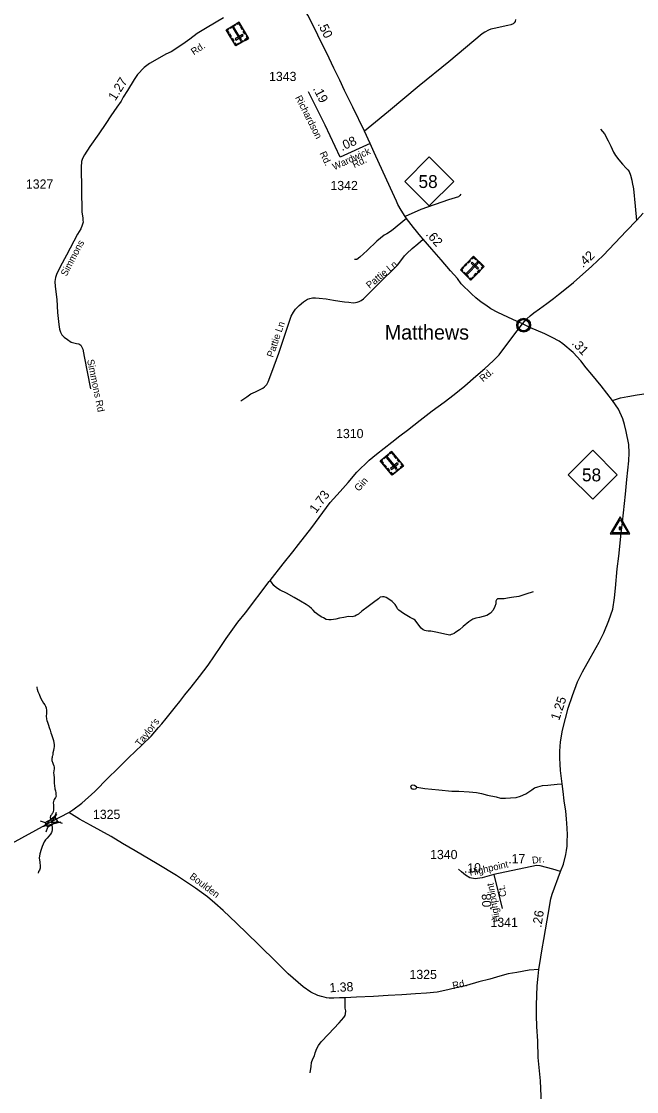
# Model space of a CAD drawing. Extents: x 2220236 to 2384410, y 720751 to 894131.
# Drawn here: x 2277880 to 2286237, y 831981 to 846519 of the extents above; entities that cross this region are included whole.
import ezdxf

# ---------------------------------------------------------------- set-up
doc = ezdxf.new("R2010")
doc.units = 0
doc.layers.add('Default', color=7, linetype='Continuous')

msp = doc.modelspace()

# ---------------------------------------------------------------- linework, layer by layer
at = {"layer": 'Default'}
for p, q in [((2278732, 841968), (2278817, 841529)), ((2278336, 835709), (2278356, 835775)), ((2278137, 835657), (2278203, 835637)), ((2278217, 835509), (2278237, 835575)), ((2278369, 835649), (2278435, 835629)), ((2284297, 834930), (2284410, 834469))]:
    msp.add_line(p, q, dxfattribs=at)
for points in [[(2282616, 844862), (2282542, 845029), (2282382, 845354), (2282268, 845580), (2282204, 845722), (2282126, 845883), (2282027, 846086), (2281958, 846230), (2281855, 846435), (2281769, 846605), (2281665, 846777), (2281569, 846930), (2281452, 847109), (2281389, 847193)], [(2280626, 846570), (2280403, 846438), (2280268, 846354), (2280169, 846280), (2280071, 846211), (2279914, 846107), (2279843, 846075), (2279692, 845990), (2279619, 845949), (2279548, 845895), (2279456, 845798), (2279412, 845731), (2279322, 845582), (2279264, 845489), (2279235, 845437), (2279174, 845353), (2279093, 845236), (2279028, 845131), (2278933, 844991), (2278811, 844820), (2278736, 844705), (2278711, 844659), (2278697, 844617), (2278691, 844540), (2278703, 843931), (2278714, 843847), (2278716, 843821), (2278717, 843791), (2278707, 843749), (2278685, 843703), (2278642, 843630), (2278493, 843345), (2278406, 843184), (2278355, 843080), (2278342, 843040), (2278336, 842984), (2278339, 842916), (2278359, 842740), (2278372, 842564), (2278388, 842400), (2278398, 842337), (2278411, 842297), (2278429, 842261), (2278463, 842229), (2278504, 842200), (2278558, 842164), (2278628, 842145), (2278658, 842139), (2278674, 842131), (2278688, 842119), (2278698, 842103), (2278715, 842066), (2278732, 841968)], [(2284591, 846544), (2284587, 846516), (2284574, 846499), (2284559, 846484), (2284527, 846473), (2284487, 846462), (2284304, 846422), (2284258, 846413), (2284227, 846402), (2284177, 846374), (2284141, 846351), (2283688, 845972), (2283283, 845645), (2282868, 845296), (2282639, 845111), (2282542, 845029)], [(2282211, 844677), (2282007, 845111), (2281778, 845562)], [(2285747, 845054), (2285800, 844991), (2285851, 844895), (2285886, 844824), (2285921, 844745), (2285951, 844696), (2285994, 844641), (2286047, 844578), (2286097, 844526), (2286117, 844505), (2286135, 844478), (2286155, 844431), (2286172, 844363), (2286178, 844329), (2286193, 844247), (2286218, 844011), (2286235, 843814)], [(2282616, 844862), (2282211, 844677)], [(2284687, 842410), (2284554, 842468), (2284350, 842566), (2284259, 842615), (2284187, 842663), (2284126, 842706), (2284054, 842766), (2283992, 842819), (2283856, 842952), (2283805, 843025), (2283708, 843133), (2283581, 843281), (2283456, 843427), (2283337, 843562), (2283307, 843595), (2283204, 843720), (2283109, 843843), (2283092, 843867), (2283038, 843957), (2282995, 844034), (2282974, 844078), (2282892, 844252), (2282671, 844740), (2282616, 844862)], [(2283851, 844173), (2283835, 844153), (2283819, 844137), (2283681, 844095), (2283305, 843963), (2283092, 843867)], [(2283109, 843843), (2282909, 843675), (2282842, 843634), (2282810, 843615), (2282709, 843535), (2282579, 843409), (2282477, 843318), (2282438, 843285), (2282404, 843283)], [(2284687, 842410), (2284748, 842478), (2284790, 842518), (2284839, 842559), (2284919, 842614), (2285016, 842689), (2285106, 842753), (2285175, 842808), (2285260, 842879), (2285379, 842974), (2285629, 843194), (2285784, 843339), (2286102, 843672), (2286235, 843814), (2286325, 843913)], [(2280860, 841363), (2280940, 841419), (2280998, 841460), (2281060, 841488), (2281097, 841507), (2281131, 841523), (2281159, 841538), (2281183, 841557), (2281213, 841585), (2281232, 841622), (2281284, 841755), (2281376, 842011), (2281482, 842325), (2281546, 842517), (2281574, 842571), (2281604, 842612), (2281654, 842659), (2281714, 842711), (2281766, 842745), (2281796, 842756), (2281833, 842762), (2281876, 842765), (2281923, 842758), (2282018, 842749), (2282119, 842732), (2282207, 842717), (2282269, 842709), (2282327, 842704), (2282385, 842698), (2282418, 842702), (2282441, 842706), (2282469, 842715), (2282497, 842728), (2282529, 842749), (2282583, 842805), (2282699, 842922), (2282809, 843029), (2282906, 843126), (2282988, 843210), (2283033, 843266), (2283084, 843335), (2283117, 843367), (2283190, 843432), (2283263, 843499), (2283337, 843562)], [(2278523, 835771), (2278579, 835808), (2278700, 835897), (2278879, 836056), (2279058, 836244), (2279179, 836360), (2279278, 836458), (2279340, 836521), (2279424, 836599), (2279519, 836690), (2279643, 836809), (2279741, 836927), (2279788, 836978), (2279847, 837050), (2279919, 837139), (2279972, 837209), (2280031, 837280), (2280098, 837370), (2280186, 837477), (2280300, 837619), (2280418, 837775), (2280588, 838027), (2280663, 838136), (2280819, 838357), (2280923, 838484), (2281246, 838909), (2281257, 838922), (2281437, 839152), (2281565, 839315), (2281644, 839413), (2281824, 839644), (2282073, 839982), (2282208, 840135), (2282319, 840257), (2282438, 840394), (2282603, 840557), (2282702, 840640), (2282913, 840804), (2283020, 840891), (2283123, 840967), (2283298, 841101), (2283460, 841228), (2283623, 841348), (2283758, 841449), (2283903, 841567), (2284053, 841699), (2284176, 841805), (2284287, 841910), (2284371, 841991), (2284556, 842240), (2284687, 842410)], [(2285909, 841371), (2285756, 841567), (2285630, 841722), (2285554, 841815), (2285481, 841909), (2285374, 842022), (2285233, 842137), (2285183, 842174), (2285092, 842223), (2284990, 842273), (2284787, 842363), (2284687, 842410)], [(2285909, 841371), (2286020, 841404), (2286116, 841423), (2286243, 841445), (2286397, 841468), (2286647, 841490), (2286751, 841493), (2286875, 841489), (2287245, 841450), (2287519, 841429), (2287775, 841405), (2287835, 841400), (2288251, 841367), (2289207, 841269), (2289372, 841253), (2289755, 841209), (2290008, 841158), (2290508, 841026)], [(2285201, 834972), (2285242, 835070), (2285274, 835202), (2285284, 835258), (2285294, 835313), (2285296, 835379), (2285298, 835471), (2285294, 835559), (2285283, 835687), (2285275, 835791), (2285251, 835933), (2285239, 836058), (2285226, 836160), (2285205, 836342), (2285197, 836428), (2285193, 836512), (2285195, 836604), (2285203, 836733), (2285231, 836891), (2285273, 837049), (2285307, 837189), (2285365, 837363), (2285434, 837548), (2285500, 837682), (2285604, 837868), (2285727, 838086), (2285792, 838211), (2285860, 838381), (2285916, 838533), (2285935, 838687), (2285952, 838819), (2285974, 839084), (2285994, 839254), (2286027, 839567), (2286044, 839716), (2286086, 840099), (2286104, 840295), (2286131, 840548), (2286135, 840658), (2286131, 840770), (2286094, 840949), (2286074, 841044), (2286048, 841121), (2285990, 841251), (2285909, 841371)], [(2284833, 838772), (2284731, 838739), (2284638, 838709), (2284536, 838691), (2284483, 838682), (2284438, 838674), (2284397, 838674), (2284374, 838675), (2284362, 838675), (2284348, 838674), (2284337, 838668), (2284332, 838663), (2284327, 838653), (2284325, 838644), (2284325, 838607), (2284309, 838572), (2284287, 838519), (2284253, 838480), (2284201, 838450), (2284104, 838422), (2284055, 838412), (2284014, 838400), (2283958, 838364), (2283881, 838298), (2283832, 838252), (2283783, 838222), (2283760, 838205), (2283737, 838194), (2283718, 838189), (2283698, 838183), (2283656, 838190), (2283510, 838222), (2283440, 838234), (2283405, 838238), (2283377, 838241), (2283361, 838245), (2283338, 838252), (2283310, 838278), (2283265, 838335), (2283231, 838385), (2283208, 838401), (2283163, 838422), (2283070, 838475), (2283008, 838519), (2282991, 838537), (2282978, 838561), (2282956, 838598), (2282915, 838637), (2282859, 838679), (2282834, 838691), (2282806, 838700), (2282783, 838702), (2282755, 838696), (2282733, 838675), (2282661, 838626), (2282592, 838573), (2282504, 838507), (2282457, 838466), (2282432, 838452), (2282408, 838440), (2282373, 838431), (2282325, 838433), (2282260, 838421), (2282199, 838414), (2282153, 838401), (2282118, 838396), (2282086, 838389), (2282058, 838391), (2282020, 838396), (2281983, 838415), (2281951, 838431), (2281905, 838463), (2281871, 838489), (2281843, 838521), (2281819, 838545), (2281791, 838572), (2281748, 838596), (2281669, 838644), (2281585, 838691), (2281480, 838751), (2281395, 838795), (2281345, 838826), (2281311, 838858), (2281276, 838900), (2281257, 838922)], [(2278089, 837481), (2278089, 837468), (2278093, 837446), (2278102, 837416), (2278120, 837378), (2278141, 837330), (2278161, 837291), (2278181, 837258), (2278198, 837235), (2278206, 837215), (2278214, 837193), (2278220, 837156), (2278220, 837133), (2278219, 837109), (2278217, 837091), (2278217, 837073), (2278219, 837053), (2278221, 837039), (2278227, 837021), (2278233, 836999), (2278248, 836957), (2278256, 836925), (2278270, 836889), (2278281, 836855), (2278289, 836830), (2278304, 836792), (2278314, 836752), (2278320, 836721), (2278325, 836696), (2278324, 836674), (2278324, 836664), (2278322, 836645), (2278317, 836616), (2278309, 836582), (2278305, 836559), (2278302, 836541), (2278298, 836531), (2278296, 836518), (2278294, 836506), (2278293, 836494), (2278295, 836479), (2278307, 836444), (2278313, 836427), (2278319, 836408), (2278323, 836388), (2278325, 836370), (2278320, 836335), (2278318, 836316), (2278320, 836280), (2278324, 836250), (2278324, 836220), (2278325, 836198), (2278327, 836168), (2278329, 836137), (2278336, 836094), (2278342, 836068), (2278346, 836038), (2278348, 836014), (2278351, 835994), (2278349, 835984), (2278343, 835974), (2278335, 835963), (2278327, 835951), (2278321, 835938), (2278315, 835921), (2278313, 835903), (2278314, 835877), (2278318, 835839), (2278318, 835828), (2278318, 835814), (2278316, 835802), (2278311, 835784), (2278305, 835769), (2278299, 835759), (2278287, 835741), (2278275, 835727), (2278272, 835703), (2278287, 835642), (2278292, 835616), (2278299, 835554), (2278299, 835536), (2278295, 835514), (2278289, 835503), (2278275, 835479), (2278254, 835451), (2278230, 835424), (2278208, 835399)], [(2283253, 836116), (2283219, 836138), (2283197, 836144), (2283179, 836140), (2283169, 836128), (2283167, 836116), (2283175, 836102), (2283183, 836094), (2283199, 836092), (2283213, 836090), (2283233, 836096), (2283241, 836100), (2283253, 836116)], [(2283253, 836116), (2283360, 836100), (2283552, 836080), (2283726, 836062), (2283821, 836060), (2283961, 836052), (2284061, 836044), (2284131, 836032), (2284213, 836010), (2284328, 835986), (2284390, 835968), (2284426, 835966), (2284454, 835966), (2284522, 835970), (2284600, 835978), (2284660, 835996), (2284730, 836028), (2284815, 836080), (2284848, 836106), (2284894, 836122), (2284960, 836140), (2285032, 836144), (2285160, 836158), (2285226, 836160)], [(2278265, 835637), (2278299, 835656), (2278523, 835771)], [(2284910, 833639), (2284778, 833630), (2284609, 833600), (2284491, 833579), (2284380, 833549), (2284241, 833509), (2284095, 833470), (2283926, 833421), (2283766, 833384), (2283634, 833354), (2283528, 833333), (2283382, 833317), (2283234, 833308), (2283049, 833296), (2282862, 833285), (2282662, 833275), (2282430, 833264), (2282278, 833257), (2282203, 833253), (2282122, 833252), (2282061, 833252), (2282023, 833257), (2281992, 833263), (2281956, 833273), (2281907, 833287), (2281812, 833333), (2281708, 833405), (2281505, 833583), (2281360, 833724), (2281095, 833984), (2280800, 834270), (2280621, 834439), (2280509, 834543), (2280410, 834627), (2280246, 834744), (2279987, 834915), (2279722, 835073), (2279424, 835251), (2279255, 835353), (2279098, 835446), (2278818, 835599), (2278670, 835681), (2278523, 835771)], [(2276045, 834343), (2276146, 834426), (2276264, 834519), (2276369, 834605), (2276521, 834700), (2276882, 834881), (2278077, 835532), (2278265, 835637)], [(2278208, 835399), (2278191, 835374), (2278163, 835310), (2278149, 835268), (2278130, 835213), (2278130, 835208), (2278122, 835158), (2278127, 835127), (2278129, 835102), (2278131, 835081), (2278133, 835062), (2278135, 835044), (2278134, 835016), (2278124, 834991), (2278114, 834969), (2278106, 834948)], [(2284297, 834930), (2284137, 834886), (2284046, 834872), (2283971, 834884), (2283913, 834922), (2283859, 834966), (2283817, 835002)], [(2285201, 834972), (2285101, 835002), (2284929, 835050), (2284875, 835052), (2284297, 834930)], [(2284910, 833639), (2284938, 833809), (2284956, 833919), (2284976, 834045), (2285000, 834177), (2285022, 834311), (2285034, 834387), (2285074, 834598), (2285092, 834661), (2285201, 834972)], [(2285901, 829402), (2285785, 829557), (2285463, 830016), (2285317, 830226), (2285249, 830348), (2285174, 830485), (2285140, 830570), (2285088, 830714), (2285049, 830881), (2285033, 830958), (2285006, 831122), (2284979, 831400), (2284951, 831706), (2284930, 832126), (2284902, 832446), (2284894, 832666), (2284883, 832867), (2284876, 833013), (2284876, 833155), (2284886, 833417), (2284899, 833551), (2284910, 833639)], [(2281803, 832235), (2281815, 832323), (2281819, 832378), (2281840, 832425), (2281861, 832469), (2281872, 832506), (2281891, 832566), (2281914, 832608), (2281951, 832656), (2282053, 832761), (2282197, 832914), (2282262, 832988), (2282276, 833013), (2282282, 833039), (2282285, 833076), (2282278, 833113), (2282280, 833171), (2282278, 833257)]]:
    msp.add_lwpolyline(points, dxfattribs=at)
for points in [[(2280963, 846288), (2280792, 846187), (2280662, 846405), (2280833, 846507)], [(2280690, 846422), (2280696, 846412), (2280677, 846401), (2280698, 846366), (2280688, 846361), (2280662, 846405)], [(2280789, 846468), (2280716, 846425), (2280710, 846434), (2280783, 846478)], [(2280854, 846258), (2280870, 846267), (2280767, 846442), (2280750, 846432)], [(2280804, 846490), (2280810, 846480), (2280829, 846492), (2280850, 846457), (2280859, 846462), (2280833, 846507)], [(2280868, 846447), (2280891, 846410), (2280881, 846404), (2280859, 846441)], [(2280708, 846349), (2280730, 846312), (2280721, 846306), (2280698, 846343)], [(2280742, 846292), (2280764, 846255), (2280754, 846249), (2280732, 846287)], [(2280893, 846326), (2280883, 846342), (2280782, 846282), (2280792, 846266)], [(2280903, 846389), (2280925, 846352), (2280915, 846346), (2280893, 846383)], [(2280941, 846325), (2280931, 846320), (2280947, 846292), (2280912, 846271), (2280918, 846262), (2280963, 846288)], [(2280769, 846224), (2280779, 846230), (2280796, 846202), (2280830, 846223), (2280836, 846213), (2280792, 846187)], [(2280899, 846250), (2280855, 846224), (2280849, 846234), (2280893, 846260)], [(2283087, 844345), (2283420, 844678), (2283753, 844345), (2283420, 844012)], [(2284022, 843328), (2284164, 843188), (2283986, 843006), (2283844, 843146)], [(2283893, 843196), (2283923, 843227), (2283931, 843219), (2283901, 843188)], [(2284080, 843230), (2284066, 843243), (2283924, 843099), (2283938, 843086)], [(2283940, 843244), (2283970, 843275), (2283979, 843267), (2283948, 843236)], [(2284004, 843250), (2283991, 843237), (2284075, 843155), (2284088, 843168)], [(2283992, 843297), (2284000, 843289), (2284023, 843312), (2284052, 843283), (2284059, 843291), (2284022, 843328)], [(2284075, 843276), (2284112, 843239), (2284104, 843231), (2284067, 843268)], [(2284134, 843157), (2284126, 843165), (2284149, 843188), (2284120, 843217), (2284127, 843225), (2284164, 843188)], [(2283868, 843123), (2283876, 843131), (2283860, 843146), (2283888, 843175), (2283880, 843183), (2283844, 843146)], [(2283893, 843114), (2283954, 843054), (2283946, 843046), (2283885, 843106)], [(2284029, 843066), (2284059, 843097), (2284067, 843089), (2284037, 843058)], [(2284075, 843113), (2284105, 843144), (2284113, 843136), (2284083, 843105)], [(2283963, 843030), (2283971, 843038), (2283986, 843022), (2284015, 843051), (2284023, 843044), (2283986, 843006)], [(2284625, 842406), (2284626, 842411), (2284628, 842418), (2284631, 842425), (2284634, 842431), (2284637, 842436), (2284641, 842442), (2284645, 842446), (2284649, 842451), (2284655, 842455), (2284660, 842459), (2284665, 842462), (2284670, 842464), (2284676, 842466), (2284681, 842468), (2284686, 842469), (2284690, 842470), (2284695, 842471), (2284701, 842471), (2284705, 842471), (2284711, 842471), (2284716, 842470), (2284721, 842469), (2284726, 842468), (2284731, 842466), (2284738, 842463), (2284744, 842459), (2284749, 842456), (2284754, 842452), (2284757, 842449), (2284762, 842444), (2284765, 842439), (2284769, 842435), (2284772, 842430), (2284774, 842425), (2284776, 842420), (2284778, 842415), (2284779, 842410), (2284780, 842404), (2284781, 842399), (2284781, 842393), (2284781, 842388), (2284780, 842382), (2284779, 842376), (2284778, 842370), (2284776, 842364), (2284773, 842359), (2284770, 842353), (2284767, 842348), (2284764, 842343), (2284759, 842339), (2284754, 842334), (2284749, 842329), (2284744, 842326), (2284740, 842324), (2284733, 842320), (2284726, 842318), (2284720, 842316), (2284713, 842315), (2284709, 842314), (2284704, 842314), (2284699, 842314), (2284694, 842314), (2284689, 842315), (2284683, 842317), (2284678, 842318), (2284673, 842320), (2284669, 842322), (2284665, 842324), (2284658, 842328), (2284652, 842332), (2284647, 842337), (2284643, 842342), (2284640, 842346), (2284637, 842350), (2284633, 842357), (2284631, 842360), (2284629, 842364), (2284627, 842373), (2284625, 842380), (2284624, 842385), (2284624, 842391), (2284624, 842396), (2284624, 842402)], [(2283071, 840482), (2282918, 840354), (2282755, 840549), (2282907, 840677)], [(2282870, 840632), (2282805, 840577), (2282798, 840586), (2282863, 840640)], [(2282882, 840656), (2282889, 840647), (2282906, 840661), (2282932, 840630), (2282940, 840638), (2282907, 840677)], [(2282952, 840624), (2282980, 840591), (2282971, 840583), (2282943, 840616)], [(2285308, 840361), (2285641, 840694), (2285974, 840361), (2285641, 840028)], [(2282780, 840571), (2282787, 840562), (2282770, 840548), (2282796, 840517), (2282788, 840509), (2282755, 840549)], [(2282810, 840501), (2282838, 840468), (2282829, 840461), (2282801, 840494)], [(2282968, 840435), (2282983, 840447), (2282852, 840602), (2282838, 840590)], [(2282996, 840508), (2282984, 840522), (2282894, 840447), (2282906, 840432)], [(2282995, 840572), (2283023, 840539), (2283014, 840532), (2282987, 840565)], [(2283043, 840515), (2283034, 840508), (2283055, 840483), (2283024, 840457), (2283031, 840449), (2283071, 840482)], [(2282852, 840451), (2282880, 840418), (2282871, 840410), (2282843, 840443)], [(2282890, 840387), (2282899, 840395), (2282920, 840370), (2282951, 840396), (2282958, 840388), (2282918, 840354)], [(2283014, 840435), (2282974, 840401), (2282967, 840410), (2283007, 840443)], [(2286147, 839560), (2286013, 839787), (2285879, 839560)], [(2286121, 839573), (2285905, 839573), (2286013, 839755)], [(2286025, 839619), (2286025, 839647), (2286001, 839647), (2286001, 839619)], [(2278417, 835642), (2278181, 835583), (2278357, 835752), (2278287, 835642)], [(2278203, 835637), (2278336, 835710), (2278370, 835648), (2278237, 835575)]]:
    msp.add_lwpolyline(points, close=True, dxfattribs=at)
for centre, radius in [((2284703, 842393), 94.3), ((2284702, 842393), 76.7)]:
    msp.add_circle(centre, radius, dxfattribs=at)

# ---------------------------------------------------------------- texts
for s, height, rotation, p in [('.50', 125, 296.7913, (2281900, 846484)), ('Rd.', 95, 33.4363, (2280222, 846057)), ('1.27', 125, 57.9835, (2279155, 845432)), ('.19', 125, 296.9011, (2281837, 845606)), ('Richardson', 95, 296.9011, (2281596, 845486)), ('.08', 125, 24.543, (2282235, 844757)), ('Rd.', 95, 295.1706, (2281928, 844728)), ('Wardwick', 95, 24.5431, (2282130, 844496)), ('Rd.', 95, 24.5431, (2282401, 844526)), ('Simmons', 95, 62.3842, (2278492, 843049)), ('.62', 125, 311.4782, (2283367, 843622)), ('.42', 125, 43.0843, (2285508, 843166)), ('Pattie Ln', 95, 39.4549, (2282610, 842884)), ('Pattie Ln', 95, 71.3186, (2281299, 841948)), ('.31', 125, 313.4376, (2285348, 842141)), ('Simmons Rd', 95, 281.797, (2278771, 841918)), ('Rd.', 95, 40.6168, (2284151, 841616)), ('Gin', 95, 48.0468, (2282463, 840128)), ('1.73', 125, 53.6704, (2281882, 839828)), ('1.25', 125, 71.576, (2285184, 837014)), ("Taylor's", 95, 52.006, (2279491, 836661)), ('.10', 125, 2.0371, (2283893, 834953)), ('Highpoint', 95, 12.672, (2283976, 834910)), ('.17', 125, 0.6349, (2284494, 835082)), ('Dr.', 95, 6.9588, (2284822, 835076)), ('Boulden', 95, 323.2169, (2280156, 834885)), ('Highpoint', 95, 100.0499, (2284385, 834292)), ('.08', 125, 92.5178, (2284268, 834442)), ('Ct.', 95, 99.8511, (2284471, 834635)), ('.26', 125, 81.0331, (2284942, 834204)), ('Rd.', 95, 12.5413, (2283746, 833373)), ('1.38', 125, 2.7143, (2282067, 833330))]:
    msp.add_text(s, height=height, rotation=rotation, dxfattribs=at).set_placement(p)
for s, height, p in [('1343', 125, (2281244, 845709)), ('58', 175, (2283274, 844256)), ('1327', 125, (2277941, 844247)), ('1342', 125, (2282078, 844227)), ('Matthews', 200, (2282816, 842196)), ('1310', 125, (2282155, 840858)), ('58', 175, (2285495, 840271)), ('1325', 125, (2278852, 835684)), ('1340', 125, (2283432, 835139)), ('1341', 125, (2284252, 834218)), ('1325', 125, (2283152, 833510))]:
    msp.add_text(s, height=height, dxfattribs=at).set_placement(p)

doc.saveas('drawing.dxf')
